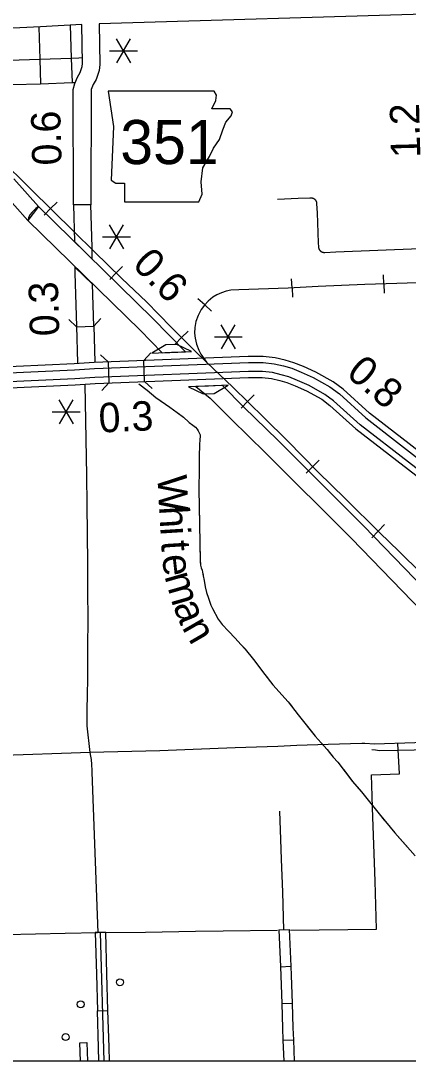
# Model space of a CAD drawing. Extents: x 309348 to 309445, y 336383 to 336484.
# Drawn here: x 309352.534 to 309353.647, y 336395.727 to 336398.714 of the extents above; entities that cross this region are included whole.
import ezdxf

# ---------------------------------------------------------------- set-up
doc = ezdxf.new("R2010")
doc.units = 0
doc.layers.add('R_Annotation', color=7, linetype='Continuous')
doc.layers.add('R_Border Notes', color=7, linetype='Continuous')

msp = doc.modelspace()

# ---------------------------------------------------------------- linework, layer by layer
at = {"layer": 'R_Annotation'}
for p, q in [((309352.829, 336398.628), (309352.809, 336398.6626)), ((309352.829, 336398.628), (309352.849, 336398.6626)), ((309352.789, 336398.628), (309352.829, 336398.628)), ((309352.829, 336398.628), (309352.809, 336398.5933)), ((309352.829, 336398.628), (309352.869, 336398.628)), ((309352.829, 336398.628), (309352.849, 336398.5933)), ((309352.6192, 336398.1749), (309352.6006, 336398.1561)), ((309352.6192, 336398.1749), (309352.6378, 336398.1937)), ((309352.7352, 336398.1857), (309352.6852, 336398.1857)), ((309352.8087, 336398.0936), (309352.7887, 336398.1283)), ((309352.8087, 336398.0936), (309352.8287, 336398.1283)), ((309352.7687, 336398.0936), (309352.8087, 336398.0936)), ((309352.8087, 336398.0936), (309352.7887, 336398.059)), ((309352.8087, 336398.0936), (309352.8487, 336398.0936)), ((309352.8087, 336398.0936), (309352.8287, 336398.059)), ((309352.688, 336398.08), (309352.7387, 336398.0298)), ((309353.4045, 336398.049), (309353.4045, 336398.049)), ((309352.74, 336397.9581), (309352.6889, 336398.0068)), ((309352.8078, 336397.99), (309352.8262, 336398.009)), ((309352.8078, 336397.99), (309352.7894, 336397.9711)), ((309353.313, 336397.9472), (309353.3117, 336397.9736)), ((309353.5769, 336397.9583), (309353.576, 336397.9847)), ((309353.313, 336397.9472), (309353.3143, 336397.9209)), ((309353.5769, 336397.9583), (309353.5777, 336397.9319)), ((309353.0621, 336397.8984), (309353.0425, 336397.9161)), ((309353.0621, 336397.8984), (309353.0817, 336397.8807)), ((309352.6936, 336397.8358), (309352.7436, 336397.8373)), ((309352.7186, 336397.8365), (309352.7186, 336397.8365)), ((309352.9957, 336397.8045), (309353.0143, 336397.8231)), ((309353.1298, 336397.8068), (309353.1098, 336397.8415)), ((309353.1298, 336397.8068), (309353.1498, 336397.8415)), ((309352.9957, 336397.8045), (309352.977, 336397.7858)), ((309353.0898, 336397.8068), (309353.1298, 336397.8068)), ((309353.1298, 336397.8068), (309353.1098, 336397.7722)), ((309353.1298, 336397.8068), (309353.1698, 336397.8068)), ((309353.1298, 336397.8068), (309353.1498, 336397.7722)), ((309352.95, 336397.7832), (309352.9099, 336397.7601)), ((309352.9099, 336397.7601), (309352.9669, 336397.7622)), ((309352.9396, 336397.7607), (309353.0068, 336397.7632)), ((309352.9823, 336397.7844), (309352.95, 336397.7832)), ((309352.9669, 336397.7622), (309353.0239, 336397.7643)), ((309353.0239, 336397.7643), (309352.9823, 336397.7844)), ((309352.7845, 336397.7344), (309352.7868, 336397.6744)), ((309352.8891, 336397.6784), (309352.8868, 336397.7384)), ((309352.7856, 336397.7044), (309352.7856, 336397.7044)), ((309352.888, 336397.7084), (309352.888, 336397.7084)), ((309353.1296, 336397.6675), (309353.0726, 336397.6654)), ((309353.0896, 336397.6444), (309353.1296, 336397.6675)), ((309353.0726, 336397.6654), (309353.0156, 336397.6633)), ((309353.0156, 336397.6633), (309353.0572, 336397.6432)), ((309353.0572, 336397.6432), (309353.0896, 336397.6444)), ((309353.1854, 336397.6207), (309353.2038, 336397.6397)), ((309352.6643, 336397.5912), (309352.6443, 336397.6259)), ((309352.6643, 336397.5912), (309352.6843, 336397.6259)), ((309353.1854, 336397.6207), (309353.1669, 336397.6018)), ((309352.6243, 336397.5912), (309352.6643, 336397.5912)), ((309352.6643, 336397.5912), (309352.6443, 336397.5566)), ((309352.6643, 336397.5912), (309352.7044, 336397.5912)), ((309352.6643, 336397.5912), (309352.6843, 336397.5566)), ((309353.3722, 336397.4341), (309353.3534, 336397.4156)), ((309353.3722, 336397.4341), (309353.391, 336397.4527)), ((309353.5603, 336397.2488), (309353.5418, 336397.23)), ((309353.5603, 336397.2488), (309353.5789, 336397.2676)), ((309352.7776, 336396.0965), (309352.7476, 336396.0962)), ((309353.2747, 336396.1036), (309353.3047, 336396.1049)), ((309353.2794, 336395.9981), (309353.3094, 336395.9994)), ((309353.2832, 336395.8927), (309353.3132, 336395.8937)), ((309352.7542, 336395.8714), (309352.7842, 336395.8723)), ((309353.2868, 336395.7871), (309353.3168, 336395.7882))]:
    msp.add_line(p, q, dxfattribs=at)
for points in [[(309353.7745, 336398.7393), (309353.775, 336398.6655), (309353.7834, 336398.2881), (309353.7333, 336398.2905), (309353.725, 336398.6647), (309353.7245, 336398.7341), (309352.759, 336398.7052), (309352.7612, 336398.5889), (309352.7591, 336398.5715), (309352.75, 336398.5454), (309352.7421, 336398.5309), (309352.7363, 336398.517), (309352.7352, 336398.1857), (309352.6852, 336398.1857), (309352.684, 336398.5168), (309352.6892, 336398.534), (309352.697, 336398.5525), (309352.7041, 336398.5657), (309352.7101, 336398.5829), (309352.7112, 336398.5914), (309352.709, 336398.7031), (309352.5905, 336398.6964), (309352.1735, 336398.6764)], [(309352.5856, 336398.6961), (309352.5887, 336398.6039)], [(309352.6755, 336398.7012), (309352.6788, 336398.607)], [(309352.499, 336398.6009), (309352.5887, 336398.6039)], [(309352.5887, 336398.6039), (309352.6788, 336398.607)], [(309352.5887, 336398.6039), (309352.5905, 336398.5335)], [(309352.6788, 336398.607), (309352.7008, 336398.6078), (309352.7108, 336398.6082)], [(309352.6788, 336398.607), (309352.6809, 336398.5366)], [(309352.5034, 336398.5328), (309352.5037, 336398.5326), (309352.5039, 336398.5324), (309352.5042, 336398.5322), (309352.5044, 336398.5321), (309352.5047, 336398.5319), (309352.5049, 336398.5318), (309352.5052, 336398.5316), (309352.5055, 336398.5315), (309352.5057, 336398.5314), (309352.506, 336398.5313), (309352.5063, 336398.5312), (309352.5066, 336398.5311), (309352.5069, 336398.531), (309352.5072, 336398.531), (309352.5075, 336398.5309), (309352.5078, 336398.5308), (309352.5081, 336398.5308), (309352.5084, 336398.5308), (309352.5087, 336398.5308), (309352.509, 336398.5308), (309352.5093, 336398.5308), (309352.5905, 336398.5335)], [(309352.5905, 336398.5335), (309352.6809, 336398.5366)], [(309352.6809, 336398.5366), (309352.6904, 336398.537)], [(309354.0136, 336396.8031), (309353.9673, 336396.8491), (309353.8897, 336396.9254), (309353.7789, 336397.0345), (309353.6843, 336397.1272), (309353.6195, 336397.1908), (309353.565, 336397.2441), (309353.4663, 336397.3417), (309353.3869, 336397.4193), (309353.2997, 336397.5077), (309353.233, 336397.5744), (309353.1427, 336397.6622), (309353.067, 336397.7337), (309353.0349, 336397.7652), (309352.9659, 336397.8343), (309352.8944, 336397.907), (309352.8241, 336397.9743), (309352.7441, 336398.0518), (309352.686, 336398.1088), (309352.563, 336398.2306), (309352.4709, 336398.3202)], [(309353.6843, 336397.1272), (309353.6195, 336397.1908), (309353.565, 336397.2441), (309353.4663, 336397.3417), (309353.3869, 336397.4193), (309353.2997, 336397.5077), (309353.233, 336397.5744), (309353.1427, 336397.6622), (309353.067, 336397.7337), (309353.0349, 336397.7652), (309352.9659, 336397.8343), (309352.8944, 336397.907), (309352.8241, 336397.9743), (309352.7441, 336398.0518), (309352.686, 336398.1088), (309352.563, 336398.2306), (309352.4709, 336398.3202)], [(309352.5138, 336398.2606), (309352.5848, 336398.1811), (309352.5543, 336398.1411), (309352.4789, 336398.2246)], [(309353.2715, 336398.2023), (309353.3308, 336398.2045), (309353.3644, 336398.2058), (309353.3649, 336398.2058), (309353.3654, 336398.2059), (309353.366, 336398.2059), (309353.3666, 336398.2059), (309353.3672, 336398.2059), (309353.3678, 336398.2059), (309353.3684, 336398.2058), (309353.3689, 336398.2058), (309353.3695, 336398.2057), (309353.3701, 336398.2056), (309353.3707, 336398.2054), (309353.3712, 336398.2053), (309353.3718, 336398.2051), (309353.3723, 336398.2049), (309353.3729, 336398.2047), (309353.3734, 336398.2045), (309353.374, 336398.2043), (309353.3745, 336398.204), (309353.375, 336398.2037), (309353.3755, 336398.2034), (309353.376, 336398.2031), (309353.3765, 336398.2028), (309353.377, 336398.2024), (309353.3774, 336398.2021), (309353.3779, 336398.2017), (309353.3783, 336398.2013), (309353.3787, 336398.2009), (309353.3791, 336398.2004), (309353.3795, 336398.2), (309353.3799, 336398.1996), (309353.3802, 336398.1991), (309353.3806, 336398.1986), (309353.3809, 336398.1981), (309353.3812, 336398.1976), (309353.3815, 336398.1971), (309353.3818, 336398.1966), (309353.382, 336398.1961), (309353.3823, 336398.1955), (309353.3825, 336398.195), (309353.3827, 336398.1944), (309353.3829, 336398.1939), (309353.383, 336398.1933), (309353.3832, 336398.1927), (309353.3833, 336398.1922), (309353.3834, 336398.1916), (309353.3835, 336398.191), (309353.3835, 336398.1904), (309353.3836, 336398.1898), (309353.3836, 336398.1893), (309353.3836, 336398.1887), (309353.3836, 336398.1882), (309353.3846, 336398.1625), (309353.388, 336398.077), (309353.3888, 336398.0653), (309353.3888, 336398.0647), (309353.3889, 336398.0641), (309353.3889, 336398.0636), (309353.389, 336398.063), (309353.3891, 336398.0624), (309353.3893, 336398.0619), (309353.3894, 336398.0613), (309353.3896, 336398.0608), (309353.3898, 336398.0602), (309353.39, 336398.0597), (309353.3902, 336398.0591), (309353.3904, 336398.0586), (309353.3907, 336398.0581), (309353.3909, 336398.0576), (309353.3912, 336398.0571), (309353.3915, 336398.0566), (309353.3919, 336398.0561), (309353.3922, 336398.0556), (309353.3926, 336398.0552), (309353.3929, 336398.0547), (309353.3933, 336398.0543), (309353.3937, 336398.0539), (309353.3941, 336398.0535), (309353.3946, 336398.0531), (309353.395, 336398.0527), (309353.3955, 336398.0524), (309353.3959, 336398.052), (309353.3964, 336398.0517), (309353.3969, 336398.0514), (309353.3974, 336398.0511), (309353.3979, 336398.0508), (309353.3984, 336398.0506), (309353.3989, 336398.0503), (309353.3995, 336398.0501), (309353.4, 336398.0499), (309353.4006, 336398.0497), (309353.4011, 336398.0496), (309353.4017, 336398.0494), (309353.4022, 336398.0493), (309353.4028, 336398.0492), (309353.4034, 336398.0491), (309353.4039, 336398.049), (309353.4045, 336398.049)], [(309352.5848, 336398.1811), (309352.5769, 336398.1752), (309352.572, 336398.1706), (309352.5662, 336398.1643), (309352.5602, 336398.1566), (309352.5556, 336398.148), (309352.5543, 336398.1411)], [(309353.0068, 336397.7632), (309352.9123, 336397.8606), (309352.5848, 336398.1811)], [(309352.6852, 336398.1857), (309352.688, 336398.08)], [(309352.7387, 336398.0298), (309352.7384, 336398.0639), (309352.7352, 336398.1857)], [(309352.5543, 336398.1411), (309352.8769, 336397.8254), (309352.9396, 336397.7607)], [(309353.4045, 336398.049), (309353.4051, 336398.049), (309353.4057, 336398.049), (309353.4062, 336398.049), (309353.4068, 336398.049), (309353.4075, 336398.0491), (309353.4388, 336398.0505), (309353.5594, 336398.0553), (309353.6802, 336398.0602), (309353.7547, 336398.0636)], [(309352.6889, 336398.0068), (309352.6891, 336397.9893), (309352.6935, 336397.837)], [(309352.7436, 336397.837), (309352.74, 336397.9581)], [(309353.7621, 336397.9649), (309353.6137, 336397.9596), (309353.522, 336397.9565), (309353.3876, 336397.9508), (309353.3017, 336397.9467), (309353.1597, 336397.9418), (309353.1373, 336397.9402), (309353.1233, 336397.9376), (309353.1104, 336397.9334), (309353.0972, 336397.9277), (309353.0851, 336397.9202), (309353.0718, 336397.9092), (309353.0616, 336397.8978), (309353.0514, 336397.8849), (309353.043, 336397.8683), (309353.0362, 336397.8509), (309353.0339, 336397.8338), (309353.0332, 336397.8168), (309353.0343, 336397.8028), (309353.0385, 336397.7853), (309353.0449, 336397.7687), (309353.0506, 336397.7566), (309353.067, 336397.7337)], [(309353.7621, 336397.9649), (309353.6137, 336397.9596), (309353.522, 336397.9565), (309353.3876, 336397.9508), (309353.3017, 336397.9467), (309353.1597, 336397.9418), (309353.1373, 336397.9402), (309353.1233, 336397.9376), (309353.1104, 336397.9334), (309353.0972, 336397.9277), (309353.0851, 336397.9202), (309353.0718, 336397.9092), (309353.0616, 336397.8978), (309353.0514, 336397.8849), (309353.043, 336397.8683), (309353.0362, 336397.8509), (309353.0339, 336397.8338), (309353.0332, 336397.8168), (309353.0343, 336397.8028), (309353.0385, 336397.7853), (309353.0449, 336397.7687), (309353.0506, 336397.7566), (309353.067, 336397.7337)], [(309352.6717, 336397.8564), (309352.6936, 336397.8358)], [(309352.7436, 336397.8373), (309352.7641, 336397.8591)], [(309352.6935, 336397.837), (309352.6966, 336397.7316)], [(309352.7436, 336397.837), (309352.7465, 336397.7351)], [(309352.9072, 336397.7604), (309352.8868, 336397.7384)], [(309354.1313, 336397.1267), (309353.5354, 336397.5879), (309353.4597, 336397.6564), (309353.4306, 336397.6778), (309353.3812, 336397.7054), (309353.3457, 336397.7212), (309353.3178, 336397.7324), (309353.2929, 336397.7395), (309353.2643, 336397.7462), (309353.2304, 336397.7499), (309353.1872, 336397.7499), (309352.7442, 336397.7329), (309352.6868, 336397.729), (309352.1859, 336397.7061)], [(309352.1866, 336397.6891), (309352.6878, 336397.712), (309352.7451, 336397.7159), (309353.1875, 336397.7329), (309353.2295, 336397.7329), (309353.2614, 336397.7294), (309353.2886, 336397.723), (309353.3123, 336397.7163), (309353.3391, 336397.7055), (309353.3736, 336397.6902), (309353.4213, 336397.6635), (309353.4489, 336397.6432), (309353.5253, 336397.5741), (309354.1085, 336397.1198)], [(309352.7845, 336397.7344), (309352.7624, 336397.7548)], [(309354.0638, 336397.1249), (309353.5085, 336397.5543), (309353.4324, 336397.623), (309353.4072, 336397.6415), (309353.3619, 336397.6669), (309353.3289, 336397.6816), (309353.3038, 336397.6916), (309353.282, 336397.6979), (309353.257, 336397.7038), (309353.2281, 336397.7069), (309353.188, 336397.7069), (309352.7465, 336397.6899), (309352.6892, 336397.6861), (309352.1877, 336397.6631)], [(309352.1884, 336397.6461), (309352.6902, 336397.6691), (309352.7474, 336397.6729), (309353.1883, 336397.6899), (309353.2272, 336397.6899), (309353.2541, 336397.687), (309353.2777, 336397.6814), (309353.2983, 336397.6755), (309353.3223, 336397.6659), (309353.3543, 336397.6517), (309353.398, 336397.6272), (309353.4217, 336397.6098), (309353.4965, 336397.5422), (309354.0341, 336397.1267)], [(309352.7181, 336397.6701), (309352.7227, 336397.4085), (309352.7236, 336397.3247), (309352.7245, 336397.2407), (309352.7253, 336397.1562), (309352.7257, 336397.0762), (309352.7261, 336396.996), (309352.7256, 336396.9159), (309352.725, 336396.8357), (309352.7241, 336396.768), (309352.7238, 336396.7463), (309352.7235, 336396.7286), (309352.7233, 336396.7052), (309352.7236, 336396.6896), (309352.7317, 336396.613)], [(309352.7664, 336397.6524), (309352.7868, 336397.6744)], [(309352.8732, 336397.6719), (309352.8969, 336397.6534), (309352.9221, 336397.6329), (309352.9617, 336397.6049), (309352.9832, 336397.5892), (309353.0009, 336397.576), (309353.0175, 336397.5606), (309353.0281, 336397.5531), (309353.0356, 336397.547), (309353.0405, 336397.5419), (309353.0435, 336397.5368), (309353.0463, 336397.5309), (309353.0486, 336397.5248), (309353.0492, 336397.5208), (309353.0484, 336397.5118), (309353.0474, 336397.4962), (309353.0459, 336397.4629), (309353.0461, 336397.4308), (309353.0451, 336397.3658), (309353.0457, 336397.3219), (309353.0476, 336397.2154), (309353.0488, 336397.1669), (309353.05, 336397.151), (309353.0514, 336397.1433), (309353.0545, 336397.1366), (309353.0559, 336397.1305), (309353.0577, 336397.1203), (309353.0602, 336397.1073), (309353.063, 336397.0888), (309353.0673, 336397.0728), (309353.0725, 336397.0559), (309353.0796, 336397.0358), (309353.0841, 336397.0267), (309353.1006, 336396.9956), (309353.1121, 336396.981), (309353.1308, 336396.9615), (309353.1491, 336396.9418), (309353.1655, 336396.9237), (309353.1787, 336396.9097), (309353.2021, 336396.8802), (309353.2348, 336396.8373), (309353.2581, 336396.8073), (309353.302, 336396.7585), (309353.3308, 336396.7209), (309353.3798, 336396.6598), (309353.4139, 336396.6218), (309353.4313, 336396.5998), (309353.4447, 336396.5852), (309353.487, 336396.5297), (309353.5124, 336396.5001), (309353.5629, 336396.4369), (309353.608, 336396.3828), (309353.6661, 336396.3166)], [(309352.8891, 336397.6784), (309352.9112, 336397.658)], [(309352.9249, 336397.6309), (309352.9617, 336397.6049), (309352.9832, 336397.5892), (309352.9893, 336397.5847)], [(309353.0096, 336397.5679), (309353.0175, 336397.5606), (309353.0281, 336397.5531), (309353.0356, 336397.547), (309353.0405, 336397.5419), (309353.0435, 336397.5368), (309353.0463, 336397.5309), (309353.0486, 336397.5248), (309353.0492, 336397.5208), (309353.0484, 336397.5118), (309353.0479, 336397.5051)], [(309353.0466, 336397.4787), (309353.0459, 336397.4629), (309353.0461, 336397.4308), (309353.0457, 336397.3995)], [(309353.0452, 336397.3731), (309353.0451, 336397.3658), (309353.0457, 336397.3219), (309353.0462, 336397.2939)], [(309353.0467, 336397.2675), (309353.0476, 336397.2154), (309353.0482, 336397.1883)], [(309353.0492, 336397.1619), (309353.05, 336397.151), (309353.0514, 336397.1433), (309353.0545, 336397.1366), (309353.0559, 336397.1305), (309353.0572, 336397.1234)], [(309353.0572, 336397.1234), (309353.0577, 336397.1203), (309353.0602, 336397.1073), (309353.063, 336397.0888), (309353.0642, 336397.0844)], [(309353.0716, 336397.0591), (309353.0725, 336397.0559), (309353.0796, 336397.0358), (309353.0841, 336397.0267), (309353.1006, 336396.9956), (309353.1063, 336396.9883)], [(309353.1239, 336396.9687), (309353.1308, 336396.9615), (309353.1491, 336396.9418), (309353.1655, 336396.9237), (309353.1778, 336396.9106)], [(309353.1943, 336396.89), (309353.2021, 336396.8802), (309353.2348, 336396.8373), (309353.2426, 336396.8272)], [(309353.2589, 336396.8064), (309353.302, 336396.7585), (309353.311, 336396.7468)], [(309353.3271, 336396.7258), (309353.3308, 336396.7209), (309353.3765, 336396.6639)], [(309354.0529, 336396.6562), (309354.0268, 336396.6553), (309353.9725, 336396.6531), (309353.8524, 336396.6477), (309353.7984, 336396.646), (309353.6658, 336396.6407), (309353.5499, 336396.6374), (309353.5219, 336396.6389), (309353.5134, 336396.6389), (309353.4167, 336396.636), (309353.3262, 336396.6333), (309353.272, 336396.6306), (309353.1494, 336396.6262), (309353.0765, 336396.6236), (309352.933, 336396.6183), (309352.7317, 336396.613)], [(309353.3939, 336396.644), (309353.4139, 336396.6218), (309353.4199, 336396.6142)], [(309353.5412, 336396.5493), (309353.6211, 336396.5516), (309353.6171, 336396.6393)], [(309353.5419, 336396.6221), (309353.5522, 336396.6206), (309353.5641, 336396.6188), (309353.6179, 336396.62), (309353.8006, 336396.6241)], [(309352.7317, 336396.613), (309352.6785, 336396.6116), (309352.5129, 336396.6052), (309352.4263, 336396.6018), (309352.2816, 336396.5971), (309352.1943, 336396.5953)], [(309352.7317, 336396.613), (309352.7341, 336396.6026), (309352.7349, 336396.5979), (309352.7356, 336396.5932), (309352.736, 336396.5884), (309352.7364, 336396.5837), (309352.7377, 336396.5571), (309352.7454, 336396.3514), (309352.7553, 336396.0952)], [(309353.4199, 336396.6142), (309353.4313, 336396.5998), (309353.4447, 336396.5852), (309353.4456, 336396.5841)], [(309353.4616, 336396.563), (309353.487, 336396.5297), (309353.5113, 336396.5013)], [(309353.3082, 336396.1035), (309353.5558, 336396.1059), (309353.5513, 336396.2437), (309353.5444, 336396.4544), (309353.5432, 336396.4881), (309353.5412, 336396.5493)], [(309353.5278, 336396.4808), (309353.5629, 336396.4369), (309353.5777, 336396.4192)], [(309353.2897, 336396.1043), (309353.2865, 336396.2124), (309353.2828, 336396.3073), (309353.2811, 336396.3638), (309353.2778, 336396.4443)], [(309353.5946, 336396.3989), (309353.608, 336396.3828), (309353.6464, 336396.339)], [(309352.2389, 336396.0795), (309352.4907, 336396.091), (309352.661, 336396.0944), (309352.7544, 336396.0963), (309352.8924, 336396.0972), (309353.0353, 336396.0999), (309353.1151, 336396.1014), (309353.271, 336396.1031)], [(309352.7476, 336396.0962), (309352.7511, 336395.977)], [(309352.7734, 336395.7269), (309352.7626, 336396.0968)], [(309352.7811, 336395.9779), (309352.7776, 336396.0965)], [(309353.2747, 336396.1036), (309353.2794, 336395.9981)], [(309353.3047, 336396.1049), (309353.3094, 336395.9994)], [(309353.2794, 336395.9981), (309353.2806, 336395.9716), (309353.2832, 336395.8927)], [(309353.3094, 336395.9994), (309353.3106, 336395.9727), (309353.3132, 336395.8937)], [(309352.7511, 336395.977), (309352.7542, 336395.8714)], [(309352.7842, 336395.8723), (309352.7811, 336395.9779)], [(309353.2832, 336395.8927), (309353.2855, 336395.8218), (309353.2868, 336395.7871)], [(309353.3132, 336395.8937), (309353.3155, 336395.8228), (309353.3168, 336395.7882)], [(309352.7572, 336395.7658), (309352.7542, 336395.8714)], [(309352.7872, 336395.7667), (309352.7842, 336395.8723)], [(309353.2868, 336395.7871), (309353.2889, 336395.7269)], [(309353.3168, 336395.7882), (309353.319, 336395.7269)], [(309352.7049, 336395.7269), (309352.7034, 336395.78), (309352.7234, 336395.7805), (309352.725, 336395.7269)], [(309352.7584, 336395.7269), (309352.7572, 336395.7658)], [(309352.7884, 336395.7269), (309352.7872, 336395.7667)]]:
    msp.add_lwpolyline(points, dxfattribs=at)
for points in [[(309352.7844, 336398.5123), (309352.7996, 336398.4108), (309352.7929, 336398.2568), (309352.8064, 336398.2483), (309352.8318, 336398.2483), (309352.8318, 336398.1941), (309353.045, 336398.1941), (309353.0552, 336398.2161), (309353.0518, 336398.2517), (309353.0569, 336398.2923), (309353.0755, 336398.3245), (309353.0873, 336398.3481), (309353.1043, 336398.3735), (309353.1144, 336398.4006), (309353.1229, 336398.4226), (309353.1381, 336398.4412), (309353.1415, 336398.4531), (309353.1347, 336398.4615), (309353.0823, 336398.4615), (309353.0941, 336398.4852), (309353.0958, 336398.5005), (309353.0888, 336398.5122)], [(309353.1129, 336397.6665), (309353.0365, 336397.6637), (309353.0777, 336397.6309), (309353.139, 336397.5691), (309353.2366, 336397.4739), (309353.484, 336397.2273), (309353.7168, 336396.987), (309354.3851, 336396.3291), (309354.4091, 336396.3756), (309353.7529, 336397.0218), (309353.5192, 336397.2628), (309353.2718, 336397.5096), (309353.1742, 336397.6046)]]:
    msp.add_lwpolyline(points, close=True, dxfattribs=at)
for centre in [(309352.8185, 336395.9536), (309352.7061, 336395.8902), (309352.6624, 336395.796)]:
    msp.add_circle(centre, 0.01, dxfattribs=at)
at = {"layer": 'R_Border Notes'}
msp.add_line((309356.3641, 336395.7269), (309347.6607, 336395.7269), dxfattribs=at)

# ---------------------------------------------------------------- texts
at = {"layer": 'R_Annotation'}
for s, height, rotation, p in [('0.6', 0.08451, 91.5068, (309352.6512, 336398.2998)), ('1.2', 0.08451, 91.473, (309353.6817, 336398.3213)), ('0.6', 0.08451, 314.1172, (309352.8513, 336398.0115)), ('0.3', 0.08451, 91.6803, (309352.6447, 336397.8096)), ('0.8', 0.08451, 319.5062, (309353.4655, 336397.6969)), ('0.3', 0.08451, 2.6207, (309352.7593, 336397.5315)), ('W', 0.0845, 273, (309352.926, 336397.408)), ('h', 0.0845, 273.4761, (309352.9307, 336397.3188)), ('i', 0.0845, 273.5787, (309352.9343, 336397.2593)), ('t', 0.0845, 273.5787, (309352.9368, 336397.2197)), ('e', 0.0845, 276.3603, (309352.9393, 336397.1787)), ('m', 0.0845, 285.9913, (309352.9459, 336397.1195)), ('a', 0.0845, 291.8609, (309352.9704, 336397.034)), ('n', 0.0845, 299.9808, (309352.9952, 336396.9722))]:
    msp.add_text(s, height=height, rotation=rotation, dxfattribs=at).set_placement(p)
msp.add_text('351', height=0.12664, dxfattribs=at).set_placement((309352.8195, 336398.3026))

doc.saveas('drawing.dxf')
